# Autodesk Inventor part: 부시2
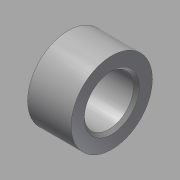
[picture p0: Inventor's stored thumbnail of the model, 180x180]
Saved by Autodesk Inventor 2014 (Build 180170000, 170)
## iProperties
Created: 2015-09
Part Number: 부시2
Material: 강철, 연강
Document SubType Name: Modeling
Designer: mduedu
Density: 7.86 g/cm^3
Description: 외주 가공
Mass: 45.4 g
Surface Area: 28.3815 cm^2
Volume: 5.77608 cm^3
Appearance: Steel
Author: mduedu
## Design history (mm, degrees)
sketch "스케치1"
  geometry: C1 r 14 at (0, 0); C2 r 8.5 at (0, 0); 1 further point
  constraints: 2 centre point, 2 coincident
  dimensions: "d0" = 28 diameter of C1; "d2" = 17 diameter of C2
extrude "돌출1" new body sketch "스케치1" distance "d3" = 15; taper "d4" = 0 deg
chamfer "모따기1" distance "d5" = 1; stored, may be unused: second distance "d6" = 2, angle "d7" = 45 deg
node "솔리드1"
